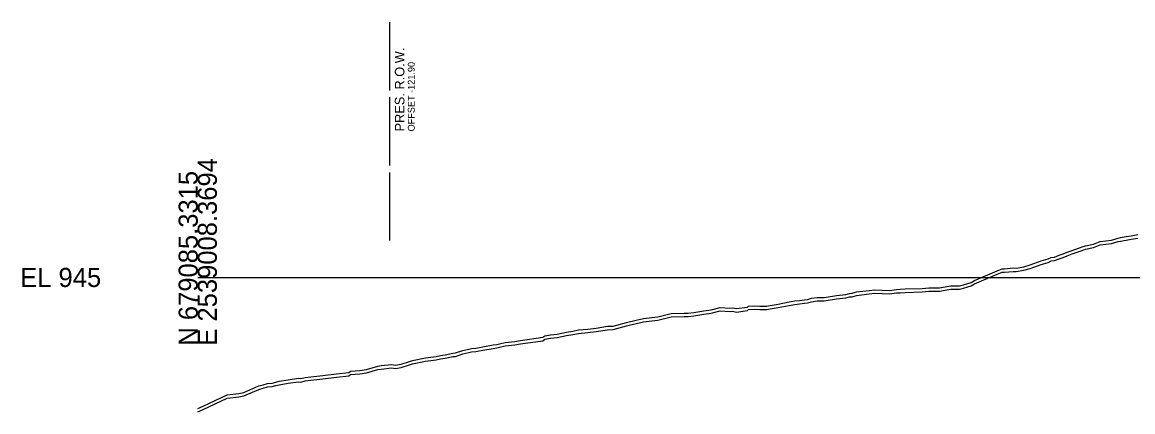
# Model space of a CAD drawing. Extents: x -26 to 2539581, y -16 to 679563.
# Drawn here: x -25.7 to 136.9, y 5980.3 to 6037.4 of the extents above; entities that cross this region are included whole.
import ezdxf

# ---------------------------------------------------------------- set-up
doc = ezdxf.new("R2010")
doc.units = 0
for name, color, linetype in [('DESIGN - SHEET - Light Grid', 7, 'Continuous'), ('SURVEY - GROUND - Bottom of Topsoil Layer', 7, 'Continuous'), ('SURVEY - GROUND - Top of Ground', 7, 'Continuous'), ('SURVEY - PROPERTY - ROW Lines', 7, 'Continuous'), ('SURVEY - PROPERTY - ROW Lines Text', 7, 'Continuous')]:
    doc.layers.add(name, color=color, linetype=linetype)

msp = doc.modelspace()

# ---------------------------------------------------------------- linework, layer by layer
at = {"layer": 'DESIGN - SHEET - Light Grid'}
msp.add_line((0, 6000), (150, 6000), dxfattribs=at)
at = {"layer": 'SURVEY - GROUND - Bottom of Topsoil Layer'}
for p, q in [((131.13, 6004.39), (132.08, 6004.76)), ((132.08, 6004.76), (133.76, 6004.97)), ((133.76, 6004.97), (134.7, 6005.25)), ((134.7, 6005.25), (135.08, 6005.33)), ((135.08, 6005.33), (135.91, 6005.48)), ((135.91, 6005.48), (136.63, 6005.6)), ((136.63, 6005.6), (137.6, 6005.77)), ((126.68, 6002.94), (127.25, 6003.18)), ((127.25, 6003.18), (127.98, 6003.46)), ((127.98, 6003.46), (129.47, 6003.97)), ((129.47, 6003.97), (129.95, 6004.14)), ((129.95, 6004.14), (131.13, 6004.39)), ((121.84, 6001.33), (123.45, 6001.91)), ((123.45, 6001.91), (124.46, 6002.21)), ((124.46, 6002.21), (124.92, 6002.41)), ((124.92, 6002.41), (125.41, 6002.48)), ((125.41, 6002.48), (126.09, 6002.75)), ((126.09, 6002.75), (126.68, 6002.94)), ((113.7, 5999.05), (117, 6000.47)), ((117, 6000.47), (117.76, 6000.76)), ((117.76, 6000.76), (118.09, 6000.78)), ((118.09, 6000.78), (119.35, 6000.89)), ((119.35, 6000.89), (119.79, 6000.86)), ((119.79, 6000.86), (120.93, 6001.06)), ((120.93, 6001.06), (121.84, 6001.33)), ((108.56, 5997.97), (110.23, 5998.27)), ((110.23, 5998.27), (111.49, 5998.27)), ((111.49, 5998.27), (112.1, 5998.43)), ((112.1, 5998.43), (112.72, 5998.6)), ((112.72, 5998.6), (113.2, 5998.78)), ((113.2, 5998.78), (113.7, 5999.05)), ((89.84, 5996.45), (90.66, 5996.57)), ((90.66, 5996.57), (91.07, 5996.56)), ((91.07, 5996.56), (91.67, 5996.57)), ((91.67, 5996.57), (93.51, 5996.85)), ((93.51, 5996.85), (94.85, 5997.01)), ((94.85, 5997.01), (95.38, 5997.15)), ((95.38, 5997.15), (95.78, 5997.18)), ((95.78, 5997.18), (96.44, 5997.37)), ((96.44, 5997.37), (98.26, 5997.59)), ((98.26, 5997.59), (99.08, 5997.68)), ((99.08, 5997.68), (101.25, 5997.61)), ((101.25, 5997.61), (102.27, 5997.74)), ((102.27, 5997.74), (102.82, 5997.76)), ((102.82, 5997.76), (103.56, 5997.81)), ((103.56, 5997.81), (106.02, 5997.88)), ((106.02, 5997.88), (107.01, 5997.99)), ((107.01, 5997.99), (108.56, 5997.97)), ((75.17, 5994.75), (76.47, 5995.11)), ((76.47, 5995.11), (77.88, 5995.02)), ((77.88, 5995.02), (78.29, 5995.04)), ((78.29, 5995.04), (78.84, 5994.93)), ((78.84, 5994.93), (80.47, 5995.15)), ((80.47, 5995.15), (80.6, 5995.31)), ((80.6, 5995.31), (81.48, 5995.36)), ((81.48, 5995.36), (82.26, 5995.3)), ((82.26, 5995.3), (83.3, 5995.3)), ((83.3, 5995.3), (83.77, 5995.39)), ((83.77, 5995.39), (84.95, 5995.6)), ((84.95, 5995.6), (86.57, 5995.91)), ((86.57, 5995.91), (87.39, 5996.05)), ((87.39, 5996.05), (88.1, 5996.12)), ((88.1, 5996.12), (88.82, 5996.22)), ((88.82, 5996.22), (89.25, 5996.26)), ((89.25, 5996.26), (89.84, 5996.45)), ((64.16, 5993.24), (65.23, 5993.49)), ((65.23, 5993.49), (66.47, 5993.63)), ((66.47, 5993.63), (67.35, 5993.73)), ((67.35, 5993.73), (69.3, 5994.24)), ((69.3, 5994.24), (71.2, 5994.29)), ((71.2, 5994.29), (71.77, 5994.27)), ((71.77, 5994.27), (72.63, 5994.37)), ((72.63, 5994.37), (74.09, 5994.6)), ((74.09, 5994.6), (75.17, 5994.75)), ((54.88, 5991.64), (55.71, 5991.81)), ((55.71, 5991.81), (57.08, 5991.91)), ((57.08, 5991.91), (58.32, 5992.07)), ((58.32, 5992.07), (59.97, 5992.34)), ((59.97, 5992.34), (60.82, 5992.36)), ((60.82, 5992.36), (62.77, 5992.91)), ((62.77, 5992.91), (64.16, 5993.24)), ((45, 5989.96), (46.4, 5990.13)), ((46.4, 5990.13), (47.22, 5990.26)), ((47.22, 5990.26), (50.49, 5990.73)), ((50.49, 5990.73), (50.8, 5990.96)), ((50.8, 5990.96), (51.63, 5991.08)), ((51.63, 5991.08), (52.6, 5991.2)), ((52.6, 5991.2), (53.98, 5991.48)), ((53.98, 5991.48), (54.88, 5991.64)), ((36.22, 5988.15), (37.35, 5988.43)), ((37.35, 5988.43), (37.71, 5988.44)), ((37.71, 5988.44), (38.8, 5988.81)), ((38.8, 5988.81), (39.69, 5989)), ((39.69, 5989), (40.09, 5989.09)), ((40.09, 5989.09), (40.69, 5989.13)), ((40.69, 5989.13), (41.74, 5989.34)), ((41.74, 5989.34), (43.24, 5989.61)), ((43.24, 5989.61), (43.76, 5989.68)), ((43.76, 5989.68), (44.19, 5989.77)), ((44.19, 5989.77), (45, 5989.96)), ((28.95, 5986.67), (29.75, 5986.81)), ((29.75, 5986.81), (30.97, 5987.18)), ((30.97, 5987.18), (31.45, 5987.32)), ((31.45, 5987.32), (33.34, 5987.73)), ((33.34, 5987.73), (34.91, 5987.92)), ((34.91, 5987.92), (35.52, 5988.06)), ((35.52, 5988.06), (36.22, 5988.15)), ((18.33, 5985.13), (20.33, 5985.38)), ((20.33, 5985.38), (22.13, 5985.57)), ((22.13, 5985.57), (22.36, 5985.77)), ((22.36, 5985.77), (23.73, 5985.87)), ((23.73, 5985.87), (24.69, 5986.01)), ((24.69, 5986.01), (26.38, 5986.52)), ((26.38, 5986.52), (26.84, 5986.58)), ((26.84, 5986.58), (28.36, 5986.74)), ((28.36, 5986.74), (28.95, 5986.67)), ((6.74, 5982.64), (8.94, 5983.6)), ((8.94, 5983.6), (9.58, 5983.77)), ((9.58, 5983.77), (10.23, 5983.96)), ((10.23, 5983.96), (10.9, 5984)), ((10.9, 5984), (11.42, 5984.17)), ((11.42, 5984.17), (11.93, 5984.28)), ((11.93, 5984.28), (13.22, 5984.52)), ((13.22, 5984.52), (14.73, 5984.73)), ((14.73, 5984.73), (15.08, 5984.68)), ((15.08, 5984.68), (15.74, 5984.86)), ((15.74, 5984.86), (16.54, 5984.96)), ((16.54, 5984.96), (18.33, 5985.13)), ((0.78, 5980.63), (4.33, 5982.3)), ((4.33, 5982.3), (6, 5982.49)), ((6, 5982.49), (6.74, 5982.64)), ((0, 5980.32), (0.78, 5980.63))]:
    msp.add_line(p, q, dxfattribs=at)
at = {"layer": 'SURVEY - GROUND - Top of Ground'}
msp.add_lwpolyline([(0, 5980.82), (0.78, 5981.13), (4.33, 5982.8), (6, 5982.99), (6.74, 5983.14), (8.94, 5984.1), (9.58, 5984.27), (10.23, 5984.46), (10.9, 5984.5), (11.42, 5984.67), (11.93, 5984.78), (13.22, 5985.02), (14.73, 5985.23), (15.08, 5985.18), (15.74, 5985.36), (16.54, 5985.46), (18.33, 5985.63), (20.33, 5985.88), (22.13, 5986.07), (22.36, 5986.27), (23.73, 5986.37), (24.69, 5986.51), (26.38, 5987.02), (26.84, 5987.08), (28.36, 5987.24), (28.95, 5987.17), (29.75, 5987.31), (30.97, 5987.68), (31.45, 5987.82), (33.34, 5988.23), (34.91, 5988.42), (35.52, 5988.56), (36.22, 5988.65), (37.35, 5988.93), (37.71, 5988.94), (38.8, 5989.31), (39.69, 5989.5), (40.09, 5989.59), (40.69, 5989.63), (41.74, 5989.84), (43.24, 5990.11), (43.76, 5990.18), (44.19, 5990.27), (45, 5990.46), (46.4, 5990.63), (47.22, 5990.76), (50.49, 5991.23), (50.8, 5991.46), (51.63, 5991.58), (52.6, 5991.7), (53.98, 5991.98), (54.88, 5992.14), (55.71, 5992.31), (57.08, 5992.41), (58.32, 5992.57), (59.97, 5992.84), (60.82, 5992.86), (62.77, 5993.41), (64.16, 5993.74), (65.23, 5993.99), (66.47, 5994.13), (67.35, 5994.23), (69.3, 5994.74), (71.2, 5994.79), (71.77, 5994.77), (72.63, 5994.87), (74.09, 5995.1), (75.17, 5995.25), (76.47, 5995.61), (77.88, 5995.52), (78.29, 5995.54), (78.84, 5995.43), (80.47, 5995.65), (80.6, 5995.81), (81.48, 5995.86), (82.26, 5995.8), (83.3, 5995.8), (83.77, 5995.89), (84.95, 5996.1), (86.57, 5996.41), (87.39, 5996.55), (88.1, 5996.62), (88.82, 5996.72), (89.25, 5996.76), (89.84, 5996.95), (90.66, 5997.07), (91.07, 5997.06), (91.67, 5997.07), (93.51, 5997.35), (94.85, 5997.51), (95.38, 5997.65), (95.78, 5997.68), (96.44, 5997.87), (98.26, 5998.09), (99.08, 5998.18), (101.25, 5998.11), (102.27, 5998.24), (102.82, 5998.26), (103.56, 5998.31), (106.02, 5998.38), (107.01, 5998.49), (108.56, 5998.47), (110.23, 5998.77), (111.49, 5998.77), (112.1, 5998.93), (112.72, 5999.1), (113.2, 5999.28), (113.7, 5999.55), (117, 6000.97), (117.76, 6001.26), (118.09, 6001.28), (119.35, 6001.39), (119.79, 6001.36), (120.93, 6001.56), (121.84, 6001.83), (123.45, 6002.41), (124.46, 6002.71), (124.92, 6002.91), (125.41, 6002.98), (126.09, 6003.25), (126.68, 6003.44), (127.25, 6003.68), (127.98, 6003.96), (129.47, 6004.47), (129.95, 6004.64), (131.13, 6004.89), (132.08, 6005.26), (133.76, 6005.47), (134.7, 6005.75), (135.08, 6005.83), (135.91, 6005.98), (136.63, 6006.1), (137.6, 6006.27)], dxfattribs=at)
at = {"layer": 'SURVEY - PROPERTY - ROW Lines'}
for p, q in [((28.1, 6027.39), (28.1, 6037.39)), ((28.1, 6016.39), (28.1, 6026.39)), ((28.1, 6005.39), (28.1, 6015.39))]:
    msp.add_line(p, q, dxfattribs=at)

# ---------------------------------------------------------------- texts
at = {"layer": 'DESIGN - SHEET - Light Grid'}
for s, p in [('E 2539008.3694', (2.8, 5990)), ('N 679085.3315', (0, 5990))]:
    msp.add_text(s, height=2.8, rotation=90, dxfattribs=at).set_placement(p)
msp.add_text('EL 945', height=2.8, dxfattribs=at).set_placement((-26, 5998.6))
at = {"layer": 'SURVEY - PROPERTY - ROW Lines Text'}
for s, height, p in [('PRES. R.O.W.', 1.4, (30.25, 6021.39)), ('OFFSET -121.90', 1, (31.75, 6021.39))]:
    msp.add_text(s, height=height, rotation=90, dxfattribs=at).set_placement(p)

doc.saveas('drawing.dxf')
